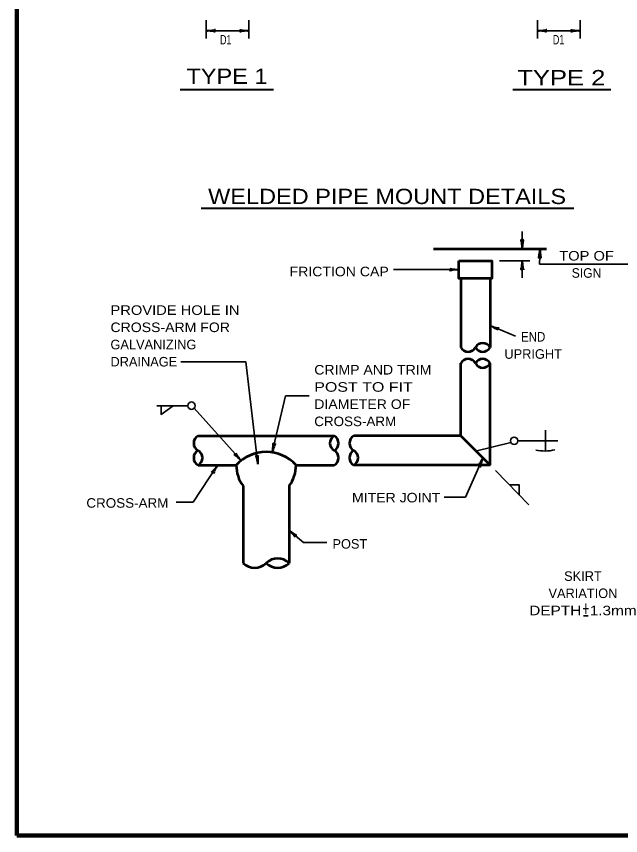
# Model space of a CAD drawing. Extents: x 11 to 867, y -284 to 260.
# Drawn here: x 68.3 to 258, y -272.1 to -14.9 of the extents above; entities that cross this region are included whole.
import ezdxf
from ezdxf.enums import TextEntityAlignment as Align

# ---------------------------------------------------------------- set-up
doc = ezdxf.new("R2010")
doc.units = 0
doc.header["$LTSCALE"] = 1.2
doc.layers.add('1', color=7, linetype='Continuous', lineweight=53)

msp = doc.modelspace()

# ---------------------------------------------------------------- linework, layer by layer
at = {"layer": '1', "lineweight": 35}
for p, q in [((127.901, -16.126), (127.901, -21.85)), ((141.265, -16.126), (141.265, -21.85)), ((231.957, -16.126), (231.957, -21.85)), ((245.321, -16.126), (245.321, -21.85)), ((127.901, -19.45), (141.265, -19.45)), ((231.957, -19.45), (245.321, -19.45)), ((227.109, -82.468), (227.109, -87.892)), ((232.558, -92.754), (232.712, -87.892)), ((220.006, -91.616), (229.51, -91.616)), ((227.109, -91.616), (227.109, -97.04)), ((207.226, -94.436), (186.68, -94.436)), ((232.558, -92.754), (262.538, -92.754)), ((217.006, -111.99), (224.988, -115.276)), ((140.364, -123.39), (119.917, -123.39)), ((144.156, -155.532), (140.364, -123.39)), ((148.614, -151.786), (152.838, -134.07)), ((152.838, -134.07), (160.202, -134.07)), ((122.106, -137.138), (112.422, -137.138)), ((138.835, -154.398), (124.102, -137.966)), ((234.428, -151.368), (234.428, -144.848)), ((212.462, -151.368), (223.538, -148.67)), ((225.72, -148.142), (238.264, -148.142)), ((214.772, -153.576), (209.284, -165.86)), ((131.446, -155.832), (123.794, -167.414)), ((218.681, -157.528), (229.194, -168.292)), ((209.284, -165.86), (202.573, -165.86)), ((123.794, -167.414), (118.513, -167.414)), ((153.928, -176.286), (158.398, -180.08)), ((158.398, -180.08), (165.769, -180.08))]:
    msp.add_line(p, q, dxfattribs=at)
at = {"layer": '1', "lineweight": 40}
for p, q in [((119.675, -37.837), (148.988, -37.837)), ((224.117, -37.837), (254.95, -37.837)), ((126.342, -75.175), (243.267, -75.175))]:
    msp.add_line(p, q, dxfattribs=at)
at = {"layer": '1'}
for p, q in [((199.23, -87.892), (234.758, -87.892)), ((207.826, -97.258), (207.826, -118.86)), ((217.006, -97.258), (217.006, -118.86)), ((207.826, -146.63), (207.826, -123.84)), ((217.006, -155.81), (217.006, -123.84)), ((125.334, -146.63), (168.103, -146.63)), ((207.826, -146.63), (174.236, -146.63)), ((207.826, -146.63), (217.006, -155.81)), ((125.334, -155.81), (137.334, -155.81)), ((156.103, -155.81), (168.103, -155.81)), ((217.006, -155.81), (174.236, -155.81)), ((139.519, -162.322), (139.519, -186.564)), ((153.919, -162.322), (153.919, -186.564))]:
    msp.add_line(p, q, dxfattribs=at)
at = {"layer": '1', "lineweight": 158}
msp.add_line((860.008, -272.101), (68.408, -272.101), dxfattribs=at)
msp.add_lwpolyline([(860.008, 254), (68.308, 253.9), (68.408, -272.101)], dxfattribs=at)
at = {"layer": '1'}
msp.add_lwpolyline([(207.226, -91.616), (217.606, -91.616), (217.606, -97.258), (207.226, -97.258)], close=True, dxfattribs=at)
at = {"layer": '1', "lineweight": 35}
for points in [[(113.718, -137.138), (113.718, -139.89), (117.528, -137.138)], [(226.202, -165.228), (226.202, -162.036), (223.084, -162.036)]]:
    msp.add_lwpolyline(points, dxfattribs=at)
for centre, radius in [((123.275, -137.139), 1.17), ((224.566, -148.142), 1.155)]:
    msp.add_circle(centre, radius, dxfattribs=at)
at = {"layer": '1'}
for centre, radius, start, end in [((214.71, -120.101), 2.609, 28.39755, 151.60246), ((210.12, -117.62), 2.609, 208.39754, 331.60245), ((214.71, -117.62), 2.609, 208.39754, 331.60245), ((210.12, -125.081), 2.609, 28.39755, 151.60246), ((214.71, -125.081), 2.609, 28.39755, 151.60246), ((214.71, -122.6), 2.609, 208.39754, 331.60245), ((126.574, -148.925), 2.609, 118.39754, 241.60245), ((169.344, -148.925), 2.609, 118.39755, 241.60246), ((166.863, -148.925), 2.609, 298.39754, 61.60245), ((175.476, -148.925), 2.609, 118.39754, 241.60245), ((126.574, -153.515), 2.609, 118.39754, 241.60245), ((124.093, -153.515), 2.609, 298.39755, 61.60246), ((146.718, -164.294), 12.651, 42.11257, 137.88743), ((166.863, -153.515), 2.609, 298.39754, 61.60245), ((175.476, -153.515), 2.609, 118.39754, 241.60245), ((172.995, -153.515), 2.609, 298.39755, 61.60246), ((147.897, -155.887), 10.564, 179.58319, 217.52937), ((145.542, -155.887), 10.564, 322.47063, 0.41681), ((150.32, -190.299), 5.187, 46.05053, 133.94947), ((143.12, -182.83), 5.187, 226.05053, 313.94947), ((150.32, -182.83), 5.187, 226.05053, 313.94947)]:
    msp.add_arc(centre, radius, start, end, dxfattribs=at)
at = {"layer": '1', "lineweight": 35}
msp.add_arc((234.123, -137.596), 13.776, 258.3589, 283.44162, dxfattribs=at)
at = {"layer": '1', "lineweight": 40}
for centre, major_axis, ratio, start_param, end_param in [((129.021, -19.661), (-1.756, 0.176), 0.07063, 3.1407148, 5.41811), ((129.021, -19.661), (-1.756, 0.176), 0.07063, 3.1407148, 5.41811), ((128.992, -19.173), (-1.786, -0.156), 0.122415, 0.8963533, 3.1415927), ((128.992, -19.173), (-1.786, -0.156), 0.122415, 0.8963533, 3.1415927), ((140.174, -19.726), (1.786, 0.156), 0.122415, 0.8963533, 3.1415927), ((140.144, -19.238), (1.756, -0.176), 0.07063, 3.1407148, 5.41811), ((233.077, -19.661), (-1.756, 0.176), 0.07063, 3.1407148, 5.41811), ((233.077, -19.661), (-1.756, 0.176), 0.07063, 3.1407148, 5.41811), ((233.048, -19.173), (-1.786, -0.156), 0.122415, 0.8963533, 3.1415927), ((233.048, -19.173), (-1.786, -0.156), 0.122415, 0.8963533, 3.1415927), ((244.23, -19.726), (1.786, 0.156), 0.122415, 0.8963533, 3.1415927), ((244.2, -19.238), (1.756, -0.176), 0.07063, 3.1407148, 5.41811), ((226.833, -86.801), (0.156, -1.786), 0.122415, 0.8963533, 3.1415927), ((226.833, -86.801), (0.156, -1.786), 0.122415, 0.8963533, 3.1415927), ((227.321, -86.772), (-0.176, -1.756), 0.07063, 3.1407148, 5.41811), ((227.321, -86.772), (-0.176, -1.756), 0.07063, 3.1407148, 5.41811), ((232.465, -89.006), (0.231, 1.75), 0.07063, 3.1407148, 5.41811), ((232.953, -88.992), (-0.1, 1.79), 0.122415, 0.8963533, 3.1415927), ((226.898, -92.737), (0.176, 1.756), 0.07063, 3.1407148, 5.41811), ((226.898, -92.737), (0.176, 1.756), 0.07063, 3.1407148, 5.41811), ((227.386, -92.708), (-0.156, 1.786), 0.122415, 0.8963533, 3.1415927), ((227.386, -92.708), (-0.156, 1.786), 0.122415, 0.8963533, 3.1415927), ((206.134, -94.713), (1.786, 0.156), 0.122415, 0.8963533, 3.1415927), ((206.134, -94.713), (1.786, 0.156), 0.122415, 0.8963533, 3.1415927), ((206.105, -94.225), (1.756, -0.176), 0.07063, 3.1407148, 5.41811), ((206.105, -94.225), (1.756, -0.176), 0.07063, 3.1407148, 5.41811), ((217.961, -112.613), (-1.557, 0.831), 0.07063, 3.1407148, 5.41811), ((218.12, -112.15), (-1.711, 0.535), 0.122415, 0.8963533, 3.1415927), ((148.598, -150.661), (-0.262, -1.773), 0.122415, 0.8963533, 3.1415927), ((149.079, -150.746), (-0.578, -1.668), 0.07063, 3.1407148, 5.41811), ((137.901, -153.77), (1.308, -1.225), 0.122415, 0.8963533, 3.1415927), ((138.245, -153.423), (1.042, -1.425), 0.07063, 3.1407148, 5.41811), ((143.753, -154.481), (0.364, -1.755), 0.122415, 0.8963533, 3.1415927), ((144.234, -154.395), (0.031, -1.765), 0.07063, 3.1407148, 5.41811), ((214.121, -154.513), (0.877, 1.532), 0.07063, 3.1407148, 5.41811), ((214.579, -154.685), (0.586, 1.694), 0.122415, 0.8963533, 3.1415927), ((130.651, -156.651), (1.115, 1.369), 0.07063, 3.1407148, 5.41811), ((131.075, -156.895), (0.854, 1.576), 0.122415, 0.8963533, 3.1415927), ((154.645, -177.173), (-1.225, 1.271), 0.07063, 3.1407148, 5.41811), ((154.938, -176.782), (-1.462, 1.036), 0.122415, 0.8963533, 3.1415927)]:
    msp.add_ellipse(centre, major_axis=major_axis, ratio=ratio, start_param=start_param, end_param=end_param, dxfattribs=at)

# ---------------------------------------------------------------- texts
at = {"layer": '1'}
for s, height, width, p in [('D1', 3, 0.7, (134.024, -23.753)), ('D1', 3, 0.7, (238.52, -23.753)), ('TYPE 1', 4.8, 1.15, (134.421, -36.11)), ('TYPE 2', 4.8, 1.25, (239.382, -36.567)), ('WELDED PIPE MOUNT DETAILS', 4.8, 1.15, (184.687, -73.844)), ('TOP OF', 3, 1.15, (247.308, -91.581)), ('FRICTION CAP', 3, 1.1, (169.644, -96.517)), ('SIGN', 3, 0.95, (247.308, -96.981)), ('END', 3, 0.9, (230.546, -117.012)), ('MITER JOINT', 3, 1.1, (187.523, -167.499)), ('CROSS-ARM', 3, 1.05, (103.155, -169.176)), ('DEPTH  1.3mm', 3, 1.2, (246.173, -202.93)), ('+', 4.8, 0.55, (247.088, -203.171))]:
    msp.add_text(s, height=height, dxfattribs=dict(at, width=width)).set_placement(p, align=Align.CENTER)
for s, width, p in [('PROVIDE HOLE IN', 1.15, (97.847, -108.636)), ('CROSS-ARM FOR', 1.1, (97.847, -114.036)), ('CRIMP AND TRIM', 1.1, (161.822, -127.36)), ('POST TO FIT', 1.25, (161.822, -132.76)), ('DIAMETER OF', 1.1, (161.822, -138.16)), ('CROSS-ARM', 1.05, (161.822, -143.56))]:
    msp.add_text(s, height=3, dxfattribs=dict(at, width=width)).set_placement(p)
for s, p in [('GALVANIZING', (97.847, -119.436)), ('DRAINAGE', (97.847, -124.836))]:
    msp.add_text(s, height=3, dxfattribs=at).set_placement(p)
for s, height, p in [('UPRIGHT', 3, (230.546, -122.412)), ('POST', 3, (172.996, -182.031)), ('SKIRT', 3, (246.173, -192.13)), ('VARIATION', 3, (246.173, -197.53)), ('-', 4.8, (247.029, -204.951))]:
    msp.add_text(s, height=height, dxfattribs=at).set_placement(p, align=Align.CENTER)

doc.saveas('drawing.dxf')
